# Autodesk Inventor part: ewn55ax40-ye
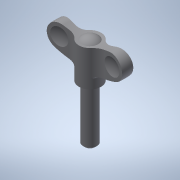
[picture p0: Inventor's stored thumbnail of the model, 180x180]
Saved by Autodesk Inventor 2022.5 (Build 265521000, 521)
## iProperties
Created: 2016-12
Part Number: ewn55ax40-ye
Material: 一般
Document SubType Name: Modeling
Designer: imaocorp
Density: 1 g/cm^3
Appearance: 既定
Author: imaocorp
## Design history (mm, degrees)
node "ewn55ax40-ye.x_t1"
node "ewn55ax40-ye"
node "Base1"
